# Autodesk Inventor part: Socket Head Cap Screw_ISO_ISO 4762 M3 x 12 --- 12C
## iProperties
Created: 2011-02
Part Number: Socket Head Cap Screw_ISO_ISO 4762 M3 x 12 --- 12C
Document SubType Name: Modeling
Designer: eric
Density: 1 g/cm^3
Author: eric
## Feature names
1. Base1
